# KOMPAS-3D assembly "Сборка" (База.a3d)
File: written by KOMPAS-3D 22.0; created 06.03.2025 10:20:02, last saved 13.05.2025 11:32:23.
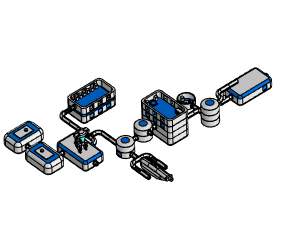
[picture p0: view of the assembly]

Document properties: Автор: Пользователь Windows; Полное имя файла: C:\Users\Student\Documents\Картошечка\База Сабнатика\База.a3d

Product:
- Component [detail]: Деталь  | qty 1  | Масса: 1.809688; source file: Большая комната\Большая комната (с шлюзом обрезанная).m3d
- Component [detail]: Деталь  | qty 1  | Масса: 1.350426; source file: Большая комната\Большая комната (с окнами обрезанная 2х).m3d
- Component [detail]: Деталь  | qty 1  | Масса: 0.308955; source file: Большая комната\Большая комната (без крыши с окнами и дыркой в полу и ещё обрезанный).m3d
- Component [detail]: Деталь  | qty 1  | Масса: 1.391303; source file: Большая комната\Большая комната (с шлюзом и коридорами ещё и обрезанная х2).m3d
- Component [detail]: Деталь  | qty 3  | Масса: 0.043049; source file: Коридор\Коридор (т-образный).m3d
- Component [detail]: Деталь  | qty 1  | Масса: 0.425402; source file: Многоцелевая комната\Многоцелевая комната (с окном и коридором).m3d
- Component [detail]: Деталь  | qty 1  | Масса: 0.115416; source file: Многоцелевая комната\Многоцелевая комната (без крыши с коридором).m3d
- Component [detail]: Деталь  | qty 1  | Масса: 0.420426; source file: Многоцелевая комната\Многоцелевая комната.m3d
- Component [detail]: Деталь  | qty 2  | Масса: 0.428066; source file: Многоцелевая комната\Многоцелевая комната (с коридором).m3d
- Component [detail]: Деталь  | qty 6  | Масса: 0.028645; source file: Коридор\Коридор.m3d
- Component [detail]: Деталь  | qty 7  | Масса: 0.022497; source file: Коридор\Коридор (уголок).m3d
- Component [detail]: Деталь  | qty 2  | Масса: 0.030965; source file: Коридор\Коридор (с лестницой).m3d
- Component [detail]: Деталь  | qty 1  | Масса: 2.240501; source file: Большая комната\Большая комната (с шлюзом, окнами и коридорам).m3d
- Component [detail]: Деталь  | qty 3  | Масса: 0.031677; source file: Коридор\Коридор (с шлюзом).m3d
- Component [detail]: Деталь  | qty 1  | Масса: 0.43308; source file: Многоцелевая комната\Многоцелевая комната (с окном и коридорами).m3d
- Component [detail]: Деталь  | qty 1  | Масса: 0.431086; source file: Многоцелевая комната\Многоцелевая комната (с шлюзом).m3d
- Component [detail]: Деталь  | qty 1  | Масса: 0.430417; source file: Многоцелевая комната\Многоцелевая комната (с окнами и коридормами).m3d
- Component [detail]: Деталь  | qty 2  | Масса: 0.009492; source file: Коридор\Коридор (без крыши).m3d
- Component [detail]: Деталь  | qty 1  | Масса: 2.257404; source file: Большая комната\Большая комната (с шлюзом и коридорами).m3d
- Component [detail]: Деталь  | qty 1  | Масса: 1.451176; source file: Стыковочная шахта\Стыковочная шахта (с коридорами).m3d
- Component [detail]: Деталь  | qty 1  | Масса: 1.441343; source file: Стыковочная шахта\Стыковочная шахта (с коридорам).m3d
- Component [detail]: Деталь  | qty 1  | source file: Деталь.m3d
- Component [detail]: Деталь  | qty 1  | Масса: 0.00858; source file: Коридор\Коридор (без крыши с проходом без арки).m3d
- Component [detail]: Деталь  | qty 1  | Масса: 0.674503; source file: Большая комната\Большая комната (без крыши с окнами и коридорам).m3d
- Component [detail]: Деталь  | qty 1  | Масса: 2.206526; source file: Большая комната\Большая комната (с окнами).m3d
- Component [detail]: Деталь  | qty 1  | Масса: 0.488336; source file: Циклоп.m3d
- Component [detail]: Деталь  | qty 1  | Масса: 0.008517; source file: Мебель\Кровать.m3d
- Component [detail]: Деталь  | qty 1  | Масса: 0.004864; source file: Мебель\Офисный стол.m3d
- Component [detail]: Деталь  | qty 3  | Масса: 0.000607; source file: Мебель\Стул.m3d
- Component [detail]: Деталь  | qty 17  | Масса: 0.005696; source file: Мебель\Шкаф.m3d
- Component [detail]: Деталь  | qty 1  | Масса: 0.001277; source file: Мебель\Стол.m3d
- Component [detail]: Деталь  | qty 1  | Масса: 0.18482; source file: КРАБ.m3d
- Part/product: Сборка
    Масса: 19.673263

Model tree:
1. Массив по сетке:1  (2 pattern instances)
     Наклон = -180; Шаг 1 = 60; Угол раствора = 90
2. Массив по сетке:2  (2 pattern instances)
     Наклон = 180; Шаг 1 = 60; Угол раствора = 90
3. Массив по сетке:3  (2 pattern instances)
     Наклон = 180; Шаг 1 = 30
4. Массив по сетке:4  (3 pattern instances)
     Наклон = 180; Шаг 1 = 25; Угол раствора = 90
5. Массив по сетке:5  (3 pattern instances)
     Наклон = 180; Шаг 1 = 27; Угол раствора = 90
6. Массив по сетке:6  (3 pattern instances)
     Наклон = 180; Шаг 1 = 30; Угол раствора = 90
7. Массив по сетке:7  (with: Элемент выдавливания:8, Элемент выдавливания:3, Элемент выдавливания:2, Элемент выдавливания:1, Элемент по траектории:2, Элемент по траектории:1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)  (7 pattern instances)
     Наклон = 180; Шаг 1 = 14; Угол раствора = 90; Ориентация = 2

Referenced files in C:\Users\Student\Documents\Картошечка\База Сабнатика\Большая комната\: Большая комната (с шлюзом обрезанная).m3d, Большая комната (с окнами обрезанная 2х).m3d, Большая комната (без крыши с окнами и дыркой в полу и ещё обрезанный).m3d, Большая комната (с шлюзом и коридорами ещё и обрезанная х2).m3d, Большая комната (с шлюзом, окнами и коридорам).m3d, Большая комната (с шлюзом и коридорами).m3d, Большая комната (без крыши с окнами и коридорам).m3d, Большая комната (с окнами).m3d
Referenced files in C:\Users\Student\Documents\Картошечка\База Сабнатика\Коридор\: Коридор (т-образный).m3d, Коридор.m3d, Коридор (уголок).m3d, Коридор (с лестницой).m3d, Коридор (с шлюзом).m3d, Коридор (без крыши).m3d, Коридор (без крыши с проходом без арки).m3d
Referenced files in C:\Users\Student\Documents\Картошечка\База Сабнатика\Многоцелевая комната\: Многоцелевая комната (с окном и коридором).m3d, Многоцелевая комната (без крыши с коридором).m3d, Многоцелевая комната.m3d, Многоцелевая комната (с коридором).m3d, Многоцелевая комната (с окном и коридорами).m3d, Многоцелевая комната (с шлюзом).m3d, Многоцелевая комната (с окнами и коридормами).m3d
Referenced files in C:\Users\Student\Documents\Картошечка\База Сабнатика\Стыковочная шахта\: Стыковочная шахта (с коридорами).m3d, Стыковочная шахта (с коридорам).m3d
Referenced files in C:\Users\Student\Documents\Картошечка\База Сабнатика\: Деталь.m3d, Циклоп.m3d, КРАБ.m3d
Referenced files in C:\Users\Student\Documents\Картошечка\База Сабнатика\Мебель\: Кровать.m3d, Офисный стол.m3d, Стул.m3d, Шкаф.m3d, Стол.m3d
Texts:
  Деталь (1)
  Деталь (2)
  Деталь (3)
  Деталь (4)
  Деталь (5)
  Деталь (6)
  Деталь (7)
  Деталь (8)
  Деталь (9)
  Деталь (10)
  Деталь (11)
  Деталь (12)
  Деталь (13)
  Деталь (14)
  Деталь (15)
  Деталь (16)
  Деталь (17)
